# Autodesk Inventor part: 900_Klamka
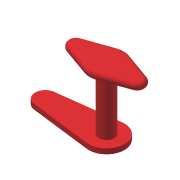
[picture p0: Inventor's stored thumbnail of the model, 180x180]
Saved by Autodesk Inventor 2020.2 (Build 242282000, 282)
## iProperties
Created: 2006-01
Part Number: 900_Klamka
Document SubType Name: Modeling
Designer: F.Stasiak
Density: 1 g/cm^3
Material: Ogólny
Appearance: Czerwony (jasny)
Manager: www.cadconsulting.pl
Company: Fabian Stasiak CAD Consulting
Author: F.Stasiak
Subject: Zbiór ćwiczeń. Autodesk Inventor 2020. Kurs podstawowy
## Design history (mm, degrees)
sketch "Szkic1"
  geometry: C1 r 7.5 at (0, 0); 1 further point
  constraints: 1 centre point, 1 coincident
  dimensions: "d0" = 15 diameter of C1
extrude "Wyciągnięcie proste1" new body sketch "Szkic1" stored distance "d1" = 55; taper "d2" = 0 deg
sketch "Szkic2"
  geometry: L1 (-30, 0)-(30, 0); L2 (-32.5, 7.071)-(-5.833, 16.499); L3 (-32.5, -7.071)-(-5.833, -16.499); L4 (5.833, -16.499)-(32.5, -7.071); L5 (5.833, 16.499)-(32.5, 7.071); C1 r 7.5 at (0, 0) reference; A1 r 17.5 centre (0, 0) between (-5.833, 16.499) and (-5.833, -16.499); A2 r 7.5 centre (-30, 0) between (-32.5, 7.071) and (-32.5, -7.071); A3 r 7.5 centre (30, 0) between (32.5, -7.071) and (32.5, 7.071); 1 further point
  constraints: 10 end point, 8 point on circle, 5 tangent, 3 centre point, 2 coincident, 2 parallel, 1 equal radius, 1 horizontal, 1 midpoint
  dimensions: "d3" = 15 diameter of A2; "d4" = 60 distance of L1.end L1.start; "d5" = 35 diameter of A1
extrude "Wyciągnięcie proste2" join sketch "Szkic2" distance "d6" = 8; taper "d7" = 0 deg
sketch "Szkic3"
  geometry: L1 (0, 0)-(60, 0); L2 (2.187, 17.363)-(61.25, 9.922); L3 (2.187, -17.363)-(61.25, -9.922); C1 r 7.5 at (0, 0) reference; A1 r 17.5 centre (0, 0) between (2.187, 17.363) and (2.187, -17.363); A2 r 10 centre (60, 0) between (61.25, 9.922) and (61.25, -9.922)
  constraints: 6 end point, 4 point on circle, 4 tangent, 2 centre point, 1 coincident, 1 horizontal
  dimensions: "d8" = 35 diameter of A1; "d9" = 20 diameter of A2; "d10" = 60 distance of L1.start L1.end
extrude "Wyciągnięcie proste3" join sketch "Szkic3" distance "d11" = 5; taper "d12" = 0 deg
fillet "Zaokrąglenie1" dims "d13" = 4
node "Bryła1"
node "Korpusy bryłowe"
node "Korpusy powierzchniowe"
